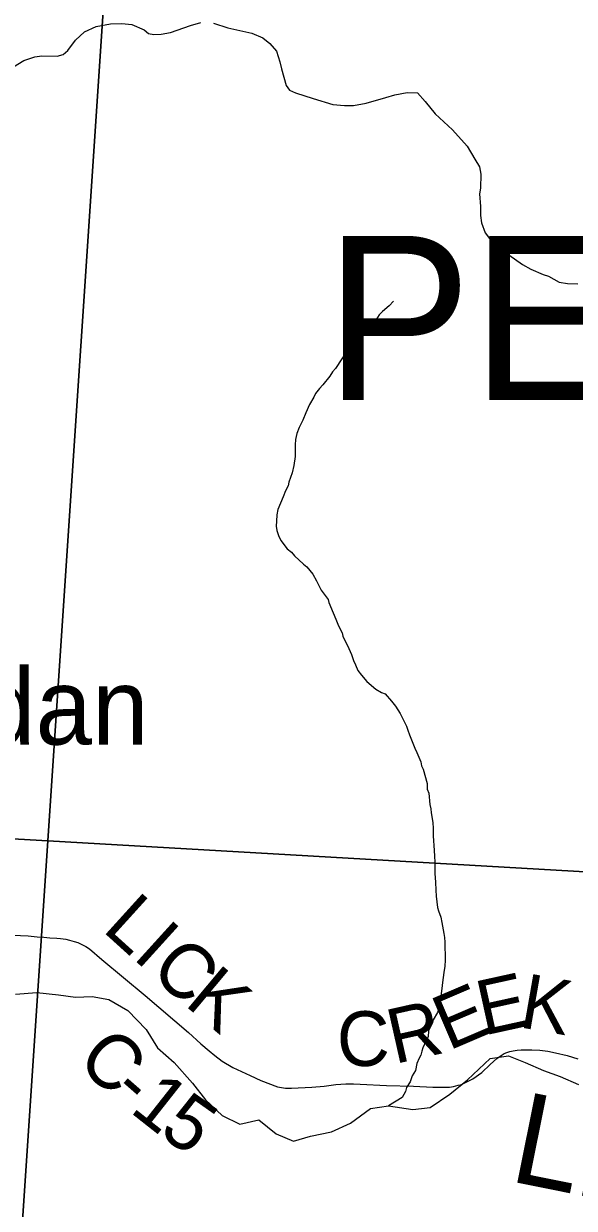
# Model space of a CAD drawing. Extents: x 0 to 45.4, y -2.2 to 22.
# Drawn here: x 3.896 to 4.467, y 17.917 to 19.147 of the extents above; entities that cross this region are included whole.
import ezdxf

# ---------------------------------------------------------------- set-up
doc = ezdxf.new("R2010")
doc.units = 0
for name, color, linetype in [('GM_X_Corporation', 7, 'Continuous'), ('GM_X_County_Road', 7, 'Continuous'), ('GM_X_County_Road_Text', 7, 'Continuous'), ('GM_X_Minor_River', 7, 'Continuous'), ('GM_X_Minor_River_Text', 7, 'Continuous'), ('GM_X_Township_Road', 7, 'Continuous'), ('GM_X_Township_Text', 7, 'Continuous'), ('GM_X_Unincorporated_Text', 7, 'Continuous')]:
    doc.layers.add(name, color=color, linetype=linetype)

msp = doc.modelspace()

# ---------------------------------------------------------------- linework, layer by layer
at = {"layer": 'GM_X_Corporation'}
for points in [[(3.9891, 19.3268), (3.9206, 18.2985), (3.1315, 18.3434)], [(3.1315, 18.3434), (3.9206, 18.2985), (3.854, 17.3067)]]:
    msp.add_lwpolyline(points, dxfattribs=at)
for points in [[(5.073, 19.2613), (5.0121, 18.2353), (3.9206, 18.2985), (3.9891, 19.3268)], [(3.9206, 18.2985), (5.0121, 18.2353), (4.9524, 17.2347), (3.854, 17.3067)]]:
    msp.add_lwpolyline(points, close=True, dxfattribs=at)
at = {"layer": 'GM_X_County_Road'}
for points in [[(3.8764, 18.2008), (3.9002, 18.1998), (3.9095, 18.1988), (3.9163, 18.1984), (3.9227, 18.1978), (3.9298, 18.1973), (3.9337, 18.197), (3.9364, 18.1966), (3.9393, 18.1962), (3.9432, 18.1953), (3.9478, 18.1939), (3.9516, 18.1927), (3.9599, 18.1887), (3.964, 18.1862), (3.9768, 18.1753), (4.0216, 18.1379), (4.0666, 18.0992), (4.0796, 18.0876), (4.088, 18.0803), (4.0941, 18.0753), (4.1017, 18.0695), (4.1128, 18.0631), (4.1215, 18.0588), (4.1305, 18.0548), (4.1418, 18.0494), (4.1592, 18.0429), (4.1674, 18.0415), (4.1734, 18.0415), (4.1948, 18.0427), (4.2074, 18.0437), (4.2196, 18.0454), (4.2301, 18.0461), (4.2378, 18.046), (4.2449, 18.0455), (4.2721, 18.0442), (4.3003, 18.0435), (4.3204, 18.0426), (4.3323, 18.0425), (4.3375, 18.0426), (4.3418, 18.0432), (4.3466, 18.0445), (4.349, 18.0451)], [(4.349, 18.0451), (4.3507, 18.0455), (4.3534, 18.0469), (4.3619, 18.0513), (4.3712, 18.0577), (4.3797, 18.0661), (4.3868, 18.0723), (4.3911, 18.0756), (4.3943, 18.0774), (4.3971, 18.0786), (4.4003, 18.0795), (4.4037, 18.0802), (4.4079, 18.0808), (4.4121, 18.0814), (4.4174, 18.0814), (4.423, 18.0813), (4.4314, 18.0809), (4.4397, 18.0798), (4.4476, 18.0782), (4.4597, 18.0756), (4.471, 18.0718)]]:
    msp.add_lwpolyline(points, dxfattribs=at)
at = {"layer": 'GM_X_Minor_River'}
for points in [[(4.2795, 18.859), (4.2749, 18.8542), (4.2679, 18.8482), (4.2645, 18.8449), (4.261, 18.8392), (4.2575, 18.8351), (4.2528, 18.8295), (4.2455, 18.8228), (4.2413, 18.8191), (4.2378, 18.8149), (4.2347, 18.8097), (4.2289, 18.8037), (4.2258, 18.7992), (4.2192, 18.7891), (4.2161, 18.7857), (4.2134, 18.7812), (4.206, 18.7722), (4.2025, 18.7684), (4.1986, 18.7632), (4.1967, 18.7591), (4.1924, 18.7515), (4.1884, 18.7429), (4.1853, 18.7353), (4.1817, 18.7278), (4.179, 18.7214), (4.1777, 18.7153), (4.1773, 18.7096), (4.1775, 18.7036), (4.1774, 18.6975), (4.1761, 18.6884), (4.1741, 18.6805), (4.1709, 18.671), (4.1701, 18.6672), (4.1673, 18.662), (4.1649, 18.6556), (4.1594, 18.6427), (4.1585, 18.6371), (4.1581, 18.6306), (4.1576, 18.6253), (4.1583, 18.6207), (4.1601, 18.6154), (4.1626, 18.6104), (4.1689, 18.6016), (4.1734, 18.5984), (4.1767, 18.5946), (4.1861, 18.5857), (4.1894, 18.583), (4.1957, 18.5753), (4.1994, 18.5684), (4.2045, 18.5588), (4.2115, 18.5492), (4.2122, 18.5458), (4.217, 18.5354), (4.2195, 18.5285), (4.2224, 18.5217), (4.2261, 18.5144), (4.2268, 18.511), (4.233, 18.4983), (4.2359, 18.4918), (4.2381, 18.4857), (4.2399, 18.4811), (4.2424, 18.4754), (4.2461, 18.4704), (4.2517, 18.4638), (4.261, 18.4561), (4.267, 18.4525), (4.2708, 18.451), (4.2775, 18.4436), (4.2816, 18.4382), (4.2863, 18.4306), (4.2929, 18.4175), (4.2944, 18.4133), (4.2962, 18.4084), (4.3016, 18.3946), (4.3038, 18.39), (4.3078, 18.3805), (4.3085, 18.3763), (4.3103, 18.3728), (4.3146, 18.3579), (4.3145, 18.3519), (4.316, 18.348), (4.3173, 18.3362), (4.3183, 18.3317), (4.3186, 18.3275), (4.3203, 18.3176), (4.3206, 18.3111), (4.3208, 18.3035), (4.3217, 18.2883), (4.322, 18.2826), (4.3223, 18.2762), (4.3224, 18.2644), (4.323, 18.2556), (4.3236, 18.2473), (4.3239, 18.2408), (4.3246, 18.2351), (4.3252, 18.229), (4.3263, 18.2256), (4.3285, 18.2191), (4.3295, 18.2137), (4.3316, 18.2023), (4.3326, 18.1981)], [(4.3326, 18.1981), (4.3329, 18.1932), (4.333, 18.1746), (4.3329, 18.1681), (4.3316, 18.1617), (4.3303, 18.1514), (4.3298, 18.145), (4.3281, 18.1317), (4.3272, 18.1268), (4.3252, 18.12), (4.3205, 18.1125), (4.3197, 18.1087), (4.3158, 18.1012), (4.3153, 18.0947), (4.3129, 18.0902), (4.3098, 18.0834), (4.309, 18.08), (4.3078, 18.0759), (4.3062, 18.0725), (4.3038, 18.0672), (4.3022, 18.06), (4.2987, 18.0544), (4.2967, 18.048), (4.2931, 18.0423), (4.2919, 18.0382), (4.2884, 18.0318), (4.2744, 18.0232)], [(3.8871, 18.1393), (3.9091, 18.1408), (3.9318, 18.1384), (3.9492, 18.1361), (3.9666, 18.1368), (3.984, 18.1337), (4.0037, 18.1222), (4.0225, 18.1024), (4.0346, 18.0834), (4.0519, 18.0681), (4.0708, 18.0468), (4.0843, 18.0293), (4.1017, 18.0132), (4.1198, 18.0041), (4.1395, 18.0085), (4.1576, 17.9941), (4.1758, 17.9864), (4.1932, 17.9916), (4.2152, 17.9961), (4.2349, 18.0052), (4.2555, 18.0203), (4.2744, 18.0232), (4.2994, 18.0193), (4.3176, 18.0215), (4.3381, 18.0351), (4.3563, 18.0503)], [(4.3563, 18.0503), (4.3799, 18.0722), (4.3988, 18.0752), (4.4162, 18.0683), (4.4351, 18.0598), (4.4525, 18.0537), (4.4714, 18.0453)]]:
    msp.add_lwpolyline(points, dxfattribs=at)
at = {"layer": 'GM_X_Township_Road'}
for points in [[(3.885, 19.1024), (3.8957, 19.109), (3.907, 19.1128), (3.9142, 19.1137), (3.9302, 19.1134), (3.9365, 19.115), (3.9413, 19.1194), (3.9494, 19.13), (3.9585, 19.1388), (3.9708, 19.1442), (3.9856, 19.147), (3.9975, 19.1473), (4.0079, 19.1464), (4.0205, 19.1407), (4.0252, 19.137), (4.0308, 19.136), (4.0381, 19.1363), (4.0481, 19.1379), (4.0686, 19.1454), (4.0796, 19.1483)], [(4.0925, 19.1477), (4.1076, 19.1429), (4.1324, 19.1373), (4.1437, 19.1326), (4.1509, 19.1266), (4.1579, 19.1187), (4.1616, 19.1077), (4.1632, 19.1002), (4.1679, 19.0829), (4.1714, 19.0782), (4.1777, 19.0753), (4.1962, 19.0694), (4.2166, 19.0634), (4.2286, 19.0621), (4.238, 19.0621), (4.2512, 19.0646), (4.2714, 19.0706), (4.2808, 19.0731), (4.2937, 19.0757), (4.3045, 19.0755), (4.3122, 19.0663), (4.3229, 19.0534), (4.3409, 19.0368), (4.356, 19.0198), (4.3638, 19.0066), (4.3686, 18.9985), (4.37, 18.9907), (4.3697, 18.9763), (4.3689, 18.9705), (4.3697, 18.9572), (4.3697, 18.948), (4.3708, 18.9402), (4.3745, 18.9299), (4.3811, 18.9214), (4.3899, 18.9159), (4.3992, 18.9071), (4.4135, 18.8971), (4.422, 18.8923), (4.4349, 18.8868), (4.4404, 18.885), (4.4515, 18.8787), (4.46, 18.8772), (4.471, 18.8769)]]:
    msp.add_lwpolyline(points, dxfattribs=at)

# ---------------------------------------------------------------- texts
at = {"layer": 'GM_X_County_Road_Text'}
for s, rotation, p in [('L', 317.8303, (3.976, 18.2056)), ('I', 317.8278, (4.0075, 18.1771)), ('C', 317.9398, (4.0249, 18.1613)), ('K', 320.1175, (4.0613, 18.1285)), ('E', 23.1261, (4.3366, 18.0801)), ('E', 12.4015, (4.3731, 18.096)), ('K', 350.0485, (4.4087, 18.105)), ('R', 12.6834, (4.2804, 18.0664)), ('C', 0.9251, (4.2211, 18.0641)), ('C', 317.4459, (3.9489, 18.0675)), ('-', 318.8513, (3.9844, 18.035)), ('1', 321.7372, (4.0044, 18.0176)), ('5', 324.7667, (4.0345, 17.994))]:
    msp.add_text(s, height=0.0568, rotation=rotation, dxfattribs=at).set_placement(p)
at = {"layer": 'GM_X_Minor_River_Text'}
msp.add_text('Lick', height=0.0947, rotation=348.6135, dxfattribs=at).set_placement((4.3978, 17.9454))
at = {"layer": 'GM_X_Township_Text'}
msp.add_text('PERRY', height=0.17045, rotation=0, dxfattribs=at).set_placement((4.2084, 18.7563))
at = {"layer": 'GM_X_Unincorporated_Text'}
msp.add_text('Sheridan', height=0.07898, rotation=0, dxfattribs=at).set_placement((3.6025, 18.3984))

doc.saveas('drawing.dxf')
